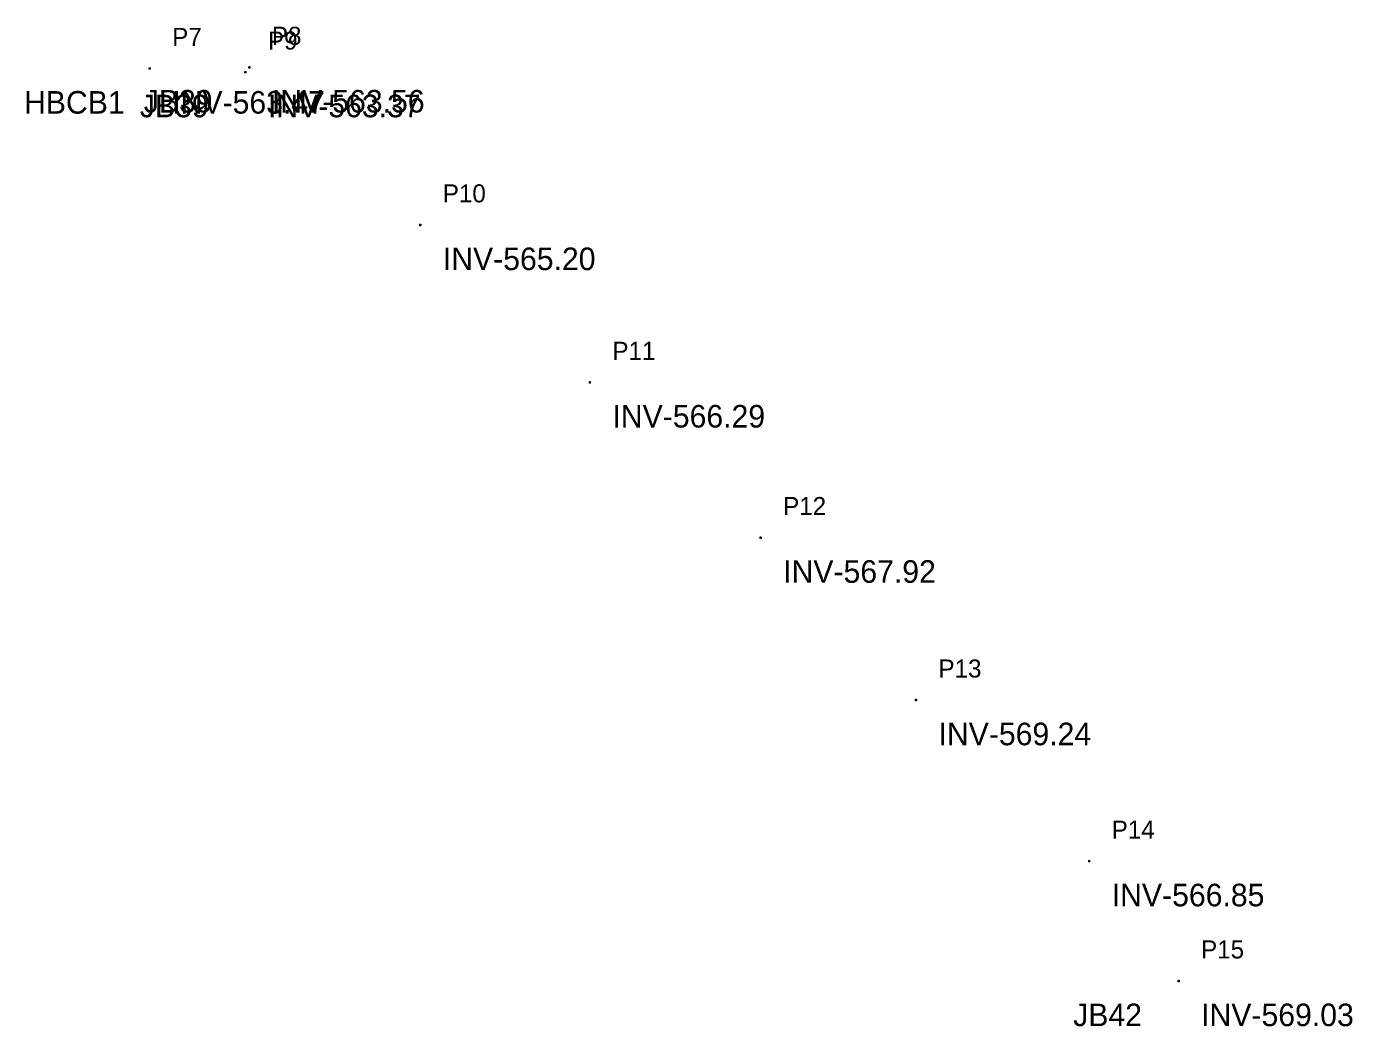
# Model space of a CAD drawing. Extents: x 1730979 to 1735363, y 649887 to 652110.
# Drawn here: x 1730978.5 to 1731272.2, y 651888.8 to 652110.4 of the extents above; entities that cross this region are included whole.
import ezdxf

# ---------------------------------------------------------------- set-up
doc = ezdxf.new("R2010")
doc.units = 0
for name, color, linetype in [('SURVEY - DRAINAGE - Storm Sewer - Points - Elevations', 7, 'Continuous'), ('SURVEY - DRAINAGE - Storm Sewer - Points - Locators', 7, 'Continuous'), ('SURVEY - DRAINAGE - Storm Sewer - Points - Numbers', 7, 'Continuous'), ('SURVEY - DRAINAGE - Storm Sewer Text', 7, 'Continuous')]:
    doc.layers.add(name, color=color, linetype=linetype)

msp = doc.modelspace()

# ---------------------------------------------------------------- linework, layer by layer
at = {"layer": 'SURVEY - DRAINAGE - Storm Sewer - Points - Locators'}
for p, q in [((1731006.04, 652101.08), (1731005.54, 652101.08)), ((1731005.79, 652100.83), (1731005.79, 652101.33)), ((1731005.79, 652101.08), (1731005.79, 652101.08)), ((1731005.79, 652101.08), (1731005.79, 652101.08)), ((1731027.24, 652100.27), (1731026.74, 652100.27)), ((1731026.99, 652100.02), (1731026.99, 652100.52)), ((1731026.99, 652100.27), (1731026.99, 652100.27)), ((1731026.99, 652100.27), (1731026.99, 652100.27)), ((1731028.12, 652101.32), (1731027.62, 652101.32)), ((1731027.87, 652101.07), (1731027.87, 652101.57)), ((1731027.87, 652101.32), (1731027.87, 652101.32)), ((1731027.87, 652101.32), (1731027.87, 652101.32)), ((1731065.98, 652066.41), (1731065.48, 652066.41)), ((1731065.73, 652066.16), (1731065.73, 652066.66)), ((1731065.73, 652066.41), (1731065.73, 652066.41)), ((1731065.73, 652066.41), (1731065.73, 652066.41)), ((1731103.55, 652031.53), (1731103.05, 652031.53)), ((1731103.3, 652031.28), (1731103.3, 652031.78)), ((1731103.3, 652031.53), (1731103.3, 652031.53)), ((1731103.3, 652031.53), (1731103.3, 652031.53)), ((1731141.37, 651997.13), (1731140.87, 651997.13)), ((1731141.12, 651996.88), (1731141.12, 651997.38)), ((1731141.12, 651997.13), (1731141.12, 651997.13)), ((1731141.12, 651997.13), (1731141.12, 651997.13)), ((1731175.78, 651961.14), (1731175.28, 651961.14)), ((1731175.53, 651960.89), (1731175.53, 651961.39)), ((1731175.53, 651961.14), (1731175.53, 651961.14)), ((1731175.53, 651961.14), (1731175.53, 651961.14)), ((1731214.15, 651925.45), (1731213.65, 651925.45)), ((1731213.9, 651925.2), (1731213.9, 651925.7)), ((1731213.9, 651925.45), (1731213.9, 651925.45)), ((1731213.9, 651925.45), (1731213.9, 651925.45)), ((1731233.95, 651898.9), (1731233.45, 651898.9)), ((1731233.7, 651898.65), (1731233.7, 651899.15)), ((1731233.7, 651898.9), (1731233.7, 651898.9)), ((1731233.7, 651898.9), (1731233.7, 651898.9))]:
    msp.add_line(p, q, dxfattribs=at)

# ---------------------------------------------------------------- texts
at = {"layer": 'SURVEY - DRAINAGE - Storm Sewer - Points - Elevations'}
for s, p in [('INV-563.47', (1731010.79, 652091.08)), ('INV-563.37', (1731031.99, 652090.27)), ('INV-563.56', (1731032.87, 652091.32)), ('INV-565.20', (1731070.73, 652056.41)), ('INV-566.29', (1731108.3, 652021.53)), ('INV-567.92', (1731146.12, 651987.13)), ('INV-569.24', (1731180.53, 651951.14)), ('INV-566.85', (1731218.9, 651915.45)), ('INV-569.03', (1731238.7, 651888.9))]:
    msp.add_text(s, height=5, dxfattribs=at).set_placement(p)
at = {"layer": 'SURVEY - DRAINAGE - Storm Sewer - Points - Numbers'}
for s, p in [('P7', (1731010.79, 652106.08)), ('P9', (1731031.99, 652105.27)), ('P8', (1731032.87, 652106.32)), ('P10', (1731070.73, 652071.41)), ('P11', (1731108.3, 652036.53)), ('P12', (1731146.12, 652002.13)), ('P13', (1731180.53, 651966.14)), ('P14', (1731218.9, 651930.45)), ('P15', (1731238.7, 651903.9))]:
    msp.add_text(s, height=4, dxfattribs=at).set_placement(p)
at = {"layer": 'SURVEY - DRAINAGE - Storm Sewer Text'}
for s, p in [('HBCB1', (1730977.96, 652091.08)), ('JB39', (1731003.61, 652090.27)), ('JB39', (1731004.49, 652091.32)), ('JB42', (1731210.36, 651888.9))]:
    msp.add_text(s, height=5, dxfattribs=at).set_placement(p)

doc.saveas('drawing.dxf')
